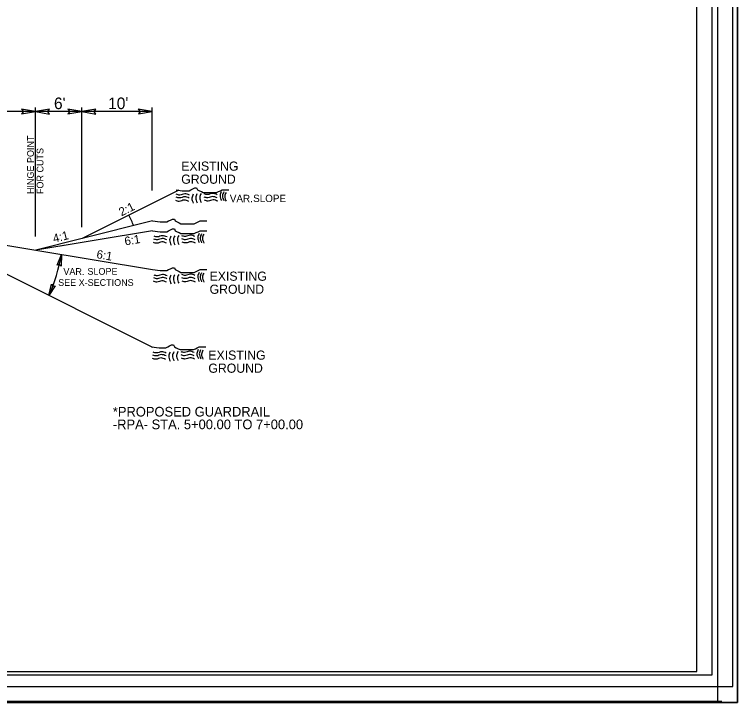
# Model space of a CAD drawing. Extents: x 2294455 to 2294795, y 719276 to 719941.
# Drawn here: x 2294677.5 to 2294794.5, y 719496.2 to 719607.5 of the extents above; entities that cross this region are included whole.
import ezdxf

# ---------------------------------------------------------------- set-up
doc = ezdxf.new("R2010")
doc.units = 0
for name, color, linetype in [('Default', 7, 'Continuous'), ('Old_Level_1', 7, 'Continuous'), ('Old_Level_11', 7, 'Continuous'), ('Old_Level_2', 7, 'Continuous'), ('Old_Level_3', 7, 'Continuous'), ('Sheet Cutting Line CELL', 7, 'Continuous'), ('Sheet Plot Border Inside CELL', 7, 'Continuous'), ('Sheet Plot Border Outside CELL', 7, 'Continuous'), ('Sheet Typical CELL', 7, 'Continuous'), ('Typical Hinge Slope Arterial CELL', 7, 'Continuous'), ('Typical Hinge Slope Interstate CELL', 7, 'Continuous')]:
    doc.layers.add(name, color=color, linetype=linetype)

msp = doc.modelspace()

# ---------------------------------------------------------------- linework, layer by layer
at = {"layer": 'Default'}
msp.add_lwpolyline([(2294454.52, 719716.17), (2294794.52, 719716.17), (2294794.52, 719496.17), (2294454.52, 719496.17)], close=True, dxfattribs=at)
at = {"layer": 'Old_Level_1'}
for p, q in [((2294704.13, 719579.03), (2294688.48, 719571.21)), ((2294699.86, 719574.06), (2294688.48, 719571.21)), ((2294662.23, 719572.46), (2294699.86, 719553.64)), ((2294662.23, 719572.46), (2294680.98, 719569.33)), ((2294699.86, 719572.48), (2294680.98, 719569.33))]:
    msp.add_line(p, q, dxfattribs=at)
at = {"layer": 'Old_Level_11'}
for p, q in [((2294680.95, 719591.75), (2294662.2, 719591.75)), ((2294680.95, 719571.54), (2294680.95, 719592.43)), ((2294688.45, 719591.75), (2294680.95, 719591.75)), ((2294688.45, 719573.05), (2294688.45, 719592.43)), ((2294699.84, 719591.75), (2294688.45, 719591.75)), ((2294699.84, 719579.01), (2294699.84, 719592.43))]:
    msp.add_line(p, q, dxfattribs=at)
for points in [[(2294678.7, 719591.37), (2294680.95, 719591.75), (2294678.69, 719592.15), (2294678.98, 719591.75)], [(2294683.2, 719592.14), (2294680.95, 719591.75), (2294683.22, 719591.35), (2294682.93, 719591.75)], [(2294686.2, 719591.37), (2294688.45, 719591.75), (2294686.19, 719592.15), (2294686.48, 719591.75)], [(2294690.7, 719592.14), (2294688.45, 719591.75), (2294690.71, 719591.35), (2294690.43, 719591.75)], [(2294697.59, 719591.37), (2294699.84, 719591.75), (2294697.58, 719592.15), (2294697.87, 719591.75)], [(2294684.45, 719566.9), (2294685.13, 719568.64), (2294685.08, 719566.76), (2294684.8, 719567.06)], [(2294684.14, 719563.58), (2294683.12, 719562.01), (2294683.55, 719563.84), (2294683.76, 719563.5)]]:
    msp.add_lwpolyline(points, close=True, dxfattribs=at)
at = {"layer": 'Old_Level_2'}
msp.add_line((2294794.52, 719716.17), (2294794.52, 719496.17), dxfattribs=at)
for points in [[(2294705.84, 719578.24), (2294705.09, 719578.46), (2294704.3, 719578.25), (2294703.72, 719578.38)], [(2294705.84, 719578.24), (2294705.09, 719578.46), (2294704.3, 719578.25), (2294703.72, 719578.38)], [(2294707.07, 719578.44), (2294706.86, 719577.82), (2294707.09, 719576.99)], [(2294707.07, 719578.44), (2294706.86, 719577.82), (2294707.09, 719576.99)], [(2294707.73, 719578.49), (2294707.52, 719577.87), (2294707.74, 719577.05)], [(2294707.73, 719578.49), (2294707.52, 719577.87), (2294707.74, 719577.05)], [(2294710.36, 719578.31), (2294709.61, 719578.53), (2294708.81, 719578.33), (2294708.24, 719578.45)], [(2294710.36, 719578.31), (2294709.61, 719578.53), (2294708.81, 719578.33), (2294708.24, 719578.45)], [(2294711.02, 719578.8), (2294710.81, 719578.17), (2294711.04, 719577.35)], [(2294711.02, 719578.8), (2294710.81, 719578.17), (2294711.04, 719577.35)], [(2294711.41, 719578.76), (2294711.2, 719578.13), (2294711.43, 719577.31)], [(2294711.41, 719578.76), (2294711.2, 719578.13), (2294711.43, 719577.31)], [(2294711.78, 719578.68), (2294711.56, 719578.06), (2294711.79, 719577.24)], [(2294711.78, 719578.68), (2294711.56, 719578.06), (2294711.79, 719577.24)], [(2294705.75, 719577.22), (2294705, 719577.44), (2294704.2, 719577.23), (2294703.63, 719577.36)], [(2294705.75, 719577.22), (2294705, 719577.44), (2294704.2, 719577.23), (2294703.63, 719577.36)], [(2294705.82, 719577.77), (2294705.07, 719577.99), (2294704.28, 719577.78), (2294703.7, 719577.91)], [(2294705.82, 719577.77), (2294705.07, 719577.99), (2294704.28, 719577.78), (2294703.7, 719577.91)], [(2294706.47, 719578.38), (2294706.25, 719577.76), (2294706.48, 719576.94)], [(2294706.47, 719578.38), (2294706.25, 719577.76), (2294706.48, 719576.94)], [(2294710.36, 719577.79), (2294709.61, 719578), (2294708.82, 719577.8), (2294708.24, 719577.93)], [(2294710.36, 719577.79), (2294709.61, 719578), (2294708.82, 719577.8), (2294708.24, 719577.93)], [(2294710.42, 719577.26), (2294709.67, 719577.47), (2294708.87, 719577.27), (2294708.3, 719577.4)], [(2294710.42, 719577.26), (2294709.67, 719577.47), (2294708.87, 719577.27), (2294708.3, 719577.4)], [(2294702.24, 719571.47), (2294701.48, 719571.68), (2294700.69, 719571.48), (2294700.12, 719571.61)], [(2294702.24, 719571.47), (2294701.48, 719571.68), (2294700.69, 719571.48), (2294700.12, 719571.61)], [(2294702.86, 719571.61), (2294702.65, 719570.99), (2294702.88, 719570.17)], [(2294702.86, 719571.61), (2294702.65, 719570.99), (2294702.88, 719570.17)], [(2294703.47, 719571.67), (2294703.25, 719571.05), (2294703.48, 719570.22)], [(2294703.47, 719571.67), (2294703.25, 719571.05), (2294703.48, 719570.22)], [(2294704.12, 719571.72), (2294703.91, 719571.1), (2294704.14, 719570.27)], [(2294704.12, 719571.72), (2294703.91, 719571.1), (2294704.14, 719570.27)], [(2294706.75, 719571.54), (2294706, 719571.76), (2294705.2, 719571.55), (2294704.63, 719571.68)], [(2294706.75, 719571.54), (2294706, 719571.76), (2294705.2, 719571.55), (2294704.63, 719571.68)], [(2294707.42, 719572.03), (2294707.2, 719571.4), (2294707.43, 719570.58)], [(2294707.42, 719572.03), (2294707.2, 719571.4), (2294707.43, 719570.58)], [(2294707.8, 719571.98), (2294707.59, 719571.36), (2294707.82, 719570.54)], [(2294707.8, 719571.98), (2294707.59, 719571.36), (2294707.82, 719570.54)], [(2294708.17, 719571.91), (2294707.96, 719571.29), (2294708.19, 719570.47)], [(2294708.17, 719571.91), (2294707.96, 719571.29), (2294708.19, 719570.47)], [(2294702.14, 719570.45), (2294701.39, 719570.67), (2294700.59, 719570.46), (2294700.02, 719570.59)], [(2294702.14, 719570.45), (2294701.39, 719570.67), (2294700.59, 719570.46), (2294700.02, 719570.59)], [(2294702.22, 719571), (2294701.46, 719571.21), (2294700.67, 719571.01), (2294700.1, 719571.14)], [(2294702.22, 719571), (2294701.46, 719571.21), (2294700.67, 719571.01), (2294700.1, 719571.14)], [(2294706.76, 719571.02), (2294706, 719571.23), (2294705.21, 719571.03), (2294704.64, 719571.16)], [(2294706.76, 719571.02), (2294706, 719571.23), (2294705.21, 719571.03), (2294704.64, 719571.16)], [(2294706.81, 719570.49), (2294706.06, 719570.7), (2294705.26, 719570.5), (2294704.69, 719570.63)], [(2294706.81, 719570.49), (2294706.06, 719570.7), (2294705.26, 719570.5), (2294704.69, 719570.63)], [(2294707.42, 719565.73), (2294707.2, 719565.11), (2294707.43, 719564.29)], [(2294707.42, 719565.73), (2294707.2, 719565.11), (2294707.43, 719564.29)], [(2294707.8, 719565.69), (2294707.59, 719565.07), (2294707.82, 719564.24)], [(2294707.8, 719565.69), (2294707.59, 719565.07), (2294707.82, 719564.24)], [(2294708.17, 719565.62), (2294707.96, 719565), (2294708.19, 719564.17)], [(2294708.17, 719565.62), (2294707.96, 719565), (2294708.19, 719564.17)], [(2294702.14, 719564.16), (2294701.39, 719564.37), (2294700.59, 719564.17), (2294700.02, 719564.3)], [(2294702.14, 719564.16), (2294701.39, 719564.37), (2294700.59, 719564.17), (2294700.02, 719564.3)], [(2294702.22, 719564.7), (2294701.46, 719564.92), (2294700.67, 719564.71), (2294700.1, 719564.84)], [(2294702.22, 719564.7), (2294701.46, 719564.92), (2294700.67, 719564.71), (2294700.1, 719564.84)], [(2294702.24, 719565.17), (2294701.48, 719565.39), (2294700.69, 719565.19), (2294700.12, 719565.31)], [(2294702.24, 719565.17), (2294701.48, 719565.39), (2294700.69, 719565.19), (2294700.12, 719565.31)], [(2294702.86, 719565.32), (2294702.65, 719564.7), (2294702.88, 719563.87)], [(2294702.86, 719565.32), (2294702.65, 719564.7), (2294702.88, 719563.87)], [(2294703.47, 719565.37), (2294703.25, 719564.75), (2294703.48, 719563.93)], [(2294703.47, 719565.37), (2294703.25, 719564.75), (2294703.48, 719563.93)], [(2294704.12, 719565.42), (2294703.91, 719564.8), (2294704.14, 719563.98)], [(2294704.12, 719565.42), (2294703.91, 719564.8), (2294704.14, 719563.98)], [(2294706.75, 719565.24), (2294706, 719565.46), (2294705.2, 719565.26), (2294704.63, 719565.39)], [(2294706.75, 719565.24), (2294706, 719565.46), (2294705.2, 719565.26), (2294704.63, 719565.39)], [(2294706.76, 719564.72), (2294706, 719564.93), (2294705.21, 719564.73), (2294704.64, 719564.86)], [(2294706.76, 719564.72), (2294706, 719564.93), (2294705.21, 719564.73), (2294704.64, 719564.86)], [(2294706.81, 719564.19), (2294706.06, 719564.41), (2294705.26, 719564.21), (2294704.69, 719564.33)], [(2294706.81, 719564.19), (2294706.06, 719564.41), (2294705.26, 719564.21), (2294704.69, 719564.33)], [(2294702.09, 719552.7), (2294701.34, 719552.91), (2294700.55, 719552.71), (2294699.97, 719552.84)], [(2294702.09, 719552.7), (2294701.34, 719552.91), (2294700.55, 719552.71), (2294699.97, 719552.84)], [(2294702.72, 719552.84), (2294702.5, 719552.22), (2294702.73, 719551.4)], [(2294702.72, 719552.84), (2294702.5, 719552.22), (2294702.73, 719551.4)], [(2294703.32, 719552.9), (2294703.11, 719552.28), (2294703.34, 719551.45)], [(2294703.32, 719552.9), (2294703.11, 719552.28), (2294703.34, 719551.45)], [(2294703.98, 719552.95), (2294703.77, 719552.33), (2294703.99, 719551.5)], [(2294703.98, 719552.95), (2294703.77, 719552.33), (2294703.99, 719551.5)], [(2294706.61, 719552.77), (2294705.86, 719552.99), (2294705.06, 719552.78), (2294704.49, 719552.91)], [(2294706.61, 719552.77), (2294705.86, 719552.99), (2294705.06, 719552.78), (2294704.49, 719552.91)], [(2294707.27, 719553.26), (2294707.06, 719552.63), (2294707.29, 719551.81)], [(2294707.27, 719553.26), (2294707.06, 719552.63), (2294707.29, 719551.81)], [(2294707.66, 719553.21), (2294707.45, 719552.59), (2294707.68, 719551.77)], [(2294707.66, 719553.21), (2294707.45, 719552.59), (2294707.68, 719551.77)], [(2294708.03, 719553.14), (2294707.81, 719552.52), (2294708.04, 719551.7)], [(2294708.03, 719553.14), (2294707.81, 719552.52), (2294708.04, 719551.7)], [(2294702, 719551.68), (2294701.25, 719551.9), (2294700.45, 719551.69), (2294699.88, 719551.82)], [(2294702, 719551.68), (2294701.25, 719551.9), (2294700.45, 719551.69), (2294699.88, 719551.82)], [(2294702.07, 719552.23), (2294701.32, 719552.44), (2294700.53, 719552.24), (2294699.95, 719552.37)], [(2294702.07, 719552.23), (2294701.32, 719552.44), (2294700.53, 719552.24), (2294699.95, 719552.37)], [(2294706.61, 719552.25), (2294705.86, 719552.46), (2294705.07, 719552.26), (2294704.49, 719552.39)], [(2294706.61, 719552.25), (2294705.86, 719552.46), (2294705.07, 719552.26), (2294704.49, 719552.39)], [(2294706.67, 719551.72), (2294705.92, 719551.93), (2294705.12, 719551.73), (2294704.55, 719551.86)], [(2294706.67, 719551.72), (2294705.92, 719551.93), (2294705.12, 719551.73), (2294704.55, 719551.86)]]:
    msp.add_spline(points, degree=3, dxfattribs=at)
at = {"layer": 'Sheet Cutting Line CELL'}
msp.add_line((2294791.96, 719496.34), (2294455.16, 719496.34), dxfattribs=at)
at = {"layer": 'Sheet Plot Border Inside CELL'}
msp.add_lwpolyline([(2294790.42, 719711.68), (2294457.12, 719711.68), (2294457.12, 719500.66), (2294790.42, 719500.66)], close=True, dxfattribs=at)
at = {"layer": 'Sheet Plot Border Outside CELL'}
for points in [[(2294793.79, 719718.76), (2294456.99, 719718.76), (2294456.99, 719498.76), (2294793.79, 719498.76)], [(2294454.52, 719496.17), (2294791.32, 719496.17), (2294791.32, 719716.17), (2294454.52, 719716.17)], [(2294794.52, 719716.17), (2294454.52, 719716.17), (2294454.52, 719496.17), (2294794.52, 719496.17)]]:
    msp.add_lwpolyline(points, close=True, dxfattribs=at)
at = {"layer": 'Sheet Typical CELL'}
msp.add_lwpolyline([(2294787.92, 719711.17), (2294487.92, 719711.17), (2294487.92, 719501.17), (2294787.92, 719501.17)], close=True, dxfattribs=at)
at = {"layer": 'Typical Hinge Slope Arterial CELL'}
msp.add_line((2294688.48, 719571.21), (2294680.98, 719569.33), dxfattribs=at)
for points in [[(2294703.72, 719579.09), (2294704.7, 719578.96), (2294705.01, 719578.96), (2294705.47, 719578.96), (2294705.78, 719578.96), (2294706.09, 719579.12), (2294706.4, 719579.27), (2294706.7, 719579.43), (2294707.01, 719579.43), (2294707.17, 719579.12), (2294707.48, 719578.96), (2294707.78, 719578.81), (2294708.09, 719578.65), (2294708.4, 719578.65), (2294708.71, 719578.65), (2294709.01, 719578.65), (2294709.32, 719578.65), (2294709.63, 719578.65), (2294709.94, 719578.65), (2294710.25, 719578.65), (2294710.55, 719578.81), (2294710.86, 719578.96), (2294711.17, 719579.12), (2294711.63, 719579.12), (2294711.94, 719579.12), (2294712.25, 719579.12)], [(2294699.86, 719574.06), (2294701.1, 719573.9), (2294701.4, 719573.9), (2294701.87, 719573.9), (2294702.17, 719573.9), (2294702.48, 719574.06), (2294702.79, 719574.21), (2294703.1, 719574.37), (2294703.41, 719574.37), (2294703.56, 719574.06), (2294703.87, 719573.9), (2294704.18, 719573.75), (2294704.48, 719573.6), (2294704.79, 719573.6), (2294705.1, 719573.6), (2294705.41, 719573.6), (2294705.72, 719573.6), (2294706.02, 719573.6), (2294706.33, 719573.6), (2294706.64, 719573.6), (2294706.95, 719573.75), (2294707.26, 719573.9), (2294707.56, 719574.06), (2294708.03, 719574.06), (2294708.33, 719574.06), (2294708.64, 719574.06)], [(2294699.86, 719572.48), (2294701.1, 719572.33), (2294701.4, 719572.33), (2294701.87, 719572.33), (2294702.17, 719572.33), (2294702.48, 719572.48), (2294702.79, 719572.64), (2294703.1, 719572.79), (2294703.41, 719572.79), (2294703.56, 719572.48), (2294703.87, 719572.33), (2294704.18, 719572.17), (2294704.48, 719572.02), (2294704.79, 719572.02), (2294705.1, 719572.02), (2294705.41, 719572.02), (2294705.72, 719572.02), (2294706.02, 719572.02), (2294706.33, 719572.02), (2294706.64, 719572.02), (2294706.95, 719572.17), (2294707.26, 719572.33), (2294707.56, 719572.48), (2294708.03, 719572.48), (2294708.33, 719572.48), (2294708.64, 719572.48)], [(2294699.86, 719566.19), (2294701.1, 719566.03), (2294701.4, 719566.03), (2294701.87, 719566.03), (2294702.17, 719566.03), (2294702.48, 719566.19), (2294702.79, 719566.34), (2294703.1, 719566.5), (2294703.41, 719566.5), (2294703.56, 719566.19), (2294703.87, 719566.03), (2294704.18, 719565.88), (2294704.48, 719565.73), (2294704.79, 719565.73), (2294705.1, 719565.73), (2294705.41, 719565.73), (2294705.72, 719565.73), (2294706.02, 719565.73), (2294706.33, 719565.73), (2294706.64, 719565.73), (2294706.95, 719565.88), (2294707.26, 719566.03), (2294707.56, 719566.19), (2294708.03, 719566.19), (2294708.33, 719566.19), (2294708.64, 719566.19)], [(2294699.72, 719553.71), (2294700.95, 719553.56), (2294701.26, 719553.56), (2294701.72, 719553.56), (2294702.03, 719553.56), (2294702.34, 719553.71), (2294702.65, 719553.87), (2294702.96, 719554.02), (2294703.26, 719554.02), (2294703.42, 719553.71), (2294703.73, 719553.56), (2294704.03, 719553.4), (2294704.34, 719553.25), (2294704.65, 719553.25), (2294704.96, 719553.25), (2294705.27, 719553.25), (2294705.57, 719553.25), (2294705.88, 719553.25), (2294706.19, 719553.25), (2294706.5, 719553.25), (2294706.81, 719553.4), (2294707.11, 719553.56), (2294707.42, 719553.71), (2294707.88, 719553.71), (2294708.19, 719553.71), (2294708.5, 719553.71)]]:
    msp.add_lwpolyline(points, dxfattribs=at)
at = {"layer": 'Typical Hinge Slope Interstate CELL'}
for p, q in [((2294688.48, 719570.58), (2294680.98, 719569.33)), ((2294680.98, 719569.33), (2294699.86, 719566.19))]:
    msp.add_line(p, q, dxfattribs=at)
for centre, radius, start, end in [((2294688.48, 719570.58), 8.77, 18.0001, 30.219), ((2294658.48, 719573.08), 27.01, 335.8047, 350.5377)]:
    msp.add_arc(centre, radius, start, end, dxfattribs=at)

# ---------------------------------------------------------------- texts
at = {"layer": 'Old_Level_1'}
for s, height, rotation, p in [('HINGE POINT ', 1.0885, 90, (2294680.68, 719578.42)), ('FOR CUTS', 1.089, 90, (2294682.23, 719578.42)), ('EXISTING', 1.484, 360, (2294704.52, 719582.19)), ('GROUND', 1.484, 360, (2294704.52, 719580.08)), ('EXISTING', 1.484, 360, (2294709.11, 719564.39)), ('GROUND', 1.484, 360, (2294709.11, 719562.28)), ('EXISTING', 1.484, 360, (2294708.91, 719551.62)), ('GROUND', 1.484, 360, (2294708.91, 719549.51))]:
    msp.add_text(s, height=height, rotation=rotation, dxfattribs=at).set_placement(p)
at = {"layer": 'Old_Level_11'}
for s, p in [('*PROPOSED GUARDRAIL ', (2294693.46, 719542.43)), ('-RPA- STA. 5+00.00 TO 7+00.00', (2294693.46, 719540.38))]:
    msp.add_text(s, height=1.5625, rotation=360, dxfattribs=at).set_placement(p)
at = {"layer": 'Old_Level_3'}
for s, p in [("6'", (2294683.94, 719592.15)), ("10'", (2294692.7, 719592.15))]:
    msp.add_text(s, height=1.875, rotation=0.1671, dxfattribs=at).set_placement(p)
at = {"layer": 'Typical Hinge Slope Arterial CELL'}
for s, height, p in [('VAR. ', 1.193, (2294712.39, 719577.1)), ('SLOPE', 1.193, (2294716.16, 719577.12)), ('VAR. ', 1.089, (2294685.46, 719565.34)), ('SLOPE', 1.089, (2294689.35, 719565.36))]:
    msp.add_text(s, height=height, dxfattribs=at).set_placement(p)
msp.add_text('4:1', height=1.375, rotation=14.0362, dxfattribs=at).set_placement((2294683.94, 719570.53))
at = {"layer": 'Typical Hinge Slope Interstate CELL'}
for s, rotation, p in [('2:1', 26.5651, (2294694.85, 719574.79)), ('6:1', 9.4623, (2294695.46, 719570.09)), ('6:1', 350.5377, (2294690.74, 719568.05))]:
    msp.add_text(s, height=1.375, rotation=rotation, dxfattribs=at).set_placement(p)
msp.add_text('SEE X-SECTIONS', height=1.0885, dxfattribs=at).set_placement((2294684.61, 719563.56))

doc.saveas('drawing.dxf')
